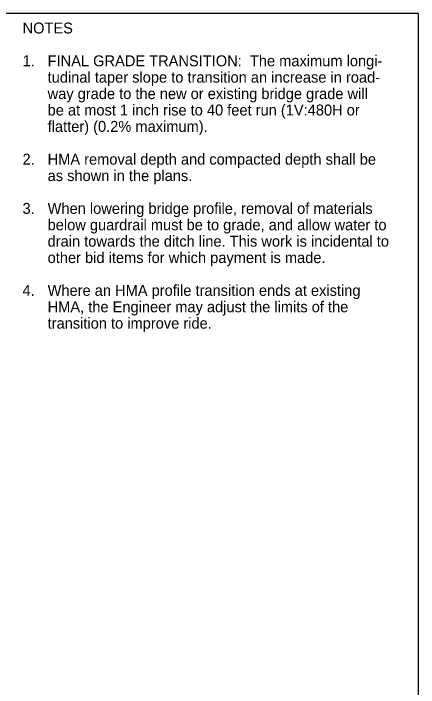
# Model space of a CAD drawing. Extents: x 99862 to 103151, y 100000 to 102076.
# Drawn here: x 102410 to 103151, y 100842 to 102076 of the extents above; entities that cross this region are included whole.
import ezdxf

# ---------------------------------------------------------------- set-up
doc = ezdxf.new("R2010")
doc.units = 0
for name, color, linetype in [('Level 1', 7, 'Continuous'), ('Level 20', 7, 'Continuous'), ('Level 60', 7, 'Continuous')]:
    doc.layers.add(name, color=color, linetype=linetype)

msp = doc.modelspace()

# ---------------------------------------------------------------- linework, layer by layer
at = {"layer": 'Level 1'}
msp.add_lwpolyline([(99862, 99999.5), (103151, 99999.5), (103151, 102075.5), (99862, 102075.5)], close=True, dxfattribs=at)
at = {"layer": 'Level 60'}
msp.add_line((103151, 102075.5), (103151, 102075.5), dxfattribs=at)

# ---------------------------------------------------------------- texts
at = {"layer": 'Level 20'}
for s, p in [('NOTES', (102426.7, 102038.9)), ('1.', (102426.7, 101978.9)), ('FINAL GRADE TRANSITION:  The maximum longi-', (102472.6, 101978.9)), ('tudinal taper slope to transition an increase in road-', (102472.6, 101948.9)), ('way grade to the new or existing bridge grade will ', (102472.6, 101918.9)), ('be at most 1 inch rise to 40 feet run (1V:480H or ', (102472.6, 101888.9)), ('flatter) (0.2% maximum). ', (102472.6, 101858.9)), ('2.', (102426.7, 101798.9)), ('HMA removal depth and compacted depth shall be', (102472.6, 101798.9)), ('as shown in the plans.', (102472.6, 101768.9)), ('3.', (102426.7, 101708.9)), ('When lowering bridge profile, removal of materials ', (102472.6, 101708.9)), ('below guardrail must be to grade, and allow water to ', (102472.6, 101678.9)), ('drain towards the ditch line. This work is incidental to', (102472.6, 101648.9)), ('other bid items for which payment is made.', (102472.6, 101618.9)), ('4.', (102426.7, 101558.9)), ('Where an HMA profile transition ends at existing ', (102472.6, 101558.9)), ('HMA, the Engineer may adjust the limits of the ', (102472.6, 101528.9)), ('transition to improve ride.', (102472.6, 101498.9))]:
    msp.add_text(s, height=20, dxfattribs=at).set_placement(p)

doc.saveas('drawing.dxf')
